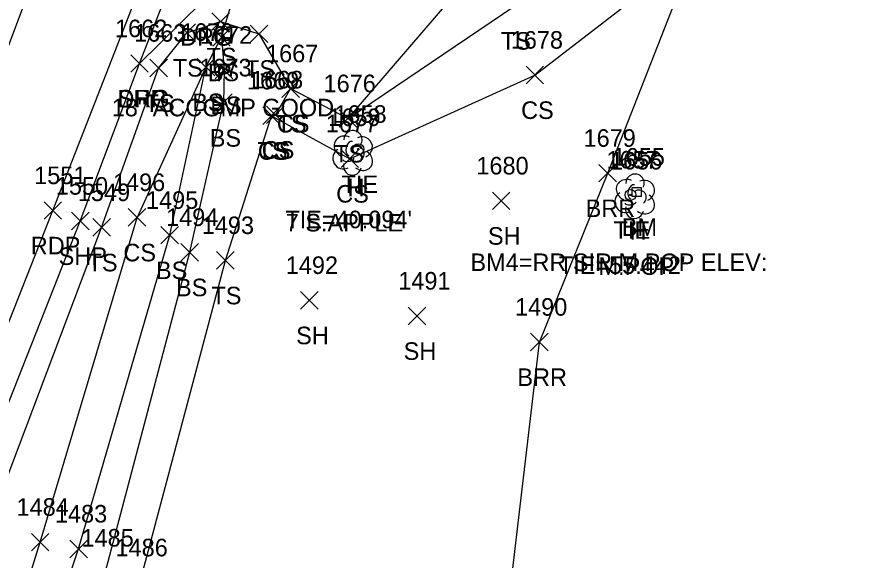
# Model space of a CAD drawing. Extents: x 1554917 to 1555870, y 813367 to 816333.
# Drawn here: x 1555258.8 to 1555355.3, y 814056.2 to 814118 of the extents above; entities that cross this region are included whole.
import ezdxf

# ---------------------------------------------------------------- set-up
doc = ezdxf.new("R2010")
doc.units = 0
for name, color, linetype in [('C_A', 7, 'Continuous'), ('C_C', 7, 'Continuous'), ('C_I', 7, 'Continuous'), ('CBP', 7, 'Continuous'), ('CPBM', 7, 'Continuous'), ('D_A', 7, 'Continuous'), ('D_C', 7, 'Continuous'), ('D_TIC', 7, 'Continuous'), ('DCP', 7, 'Continuous'), ('L_A', 7, 'Continuous'), ('L_C', 7, 'Continuous'), ('L_I', 7, 'Continuous'), ('L_TIC', 7, 'Continuous'), ('LABL', 7, 'Continuous'), ('LELB', 7, 'Continuous'), ('LTD', 7, 'Continuous'), ('P_A', 7, 'Continuous'), ('P_I', 7, 'Continuous'), ('P_TIC', 7, 'Continuous'), ('PET', 7, 'Continuous'), ('PRC', 7, 'Continuous'), ('PSP', 7, 'Continuous'), ('R_A', 7, 'Continuous'), ('R_I', 7, 'Continuous'), ('R_TIC', 7, 'Continuous'), ('RDG', 7, 'Continuous')]:
    doc.layers.add(name, color=color, linetype=linetype)

msp = doc.modelspace()

# ---------------------------------------------------------------- linework, layer by layer
at = {"layer": 'CBP'}
for centre, radius in [((1555297.714, 814102.983), 0.625), ((1555297.714, 814102.983), 0.0833), ((1555328.694, 814097.778), 0.625), ((1555328.694, 814097.778), 0.0833)]:
    msp.add_circle(centre, radius, dxfattribs=at)
at = {"layer": 'CPBM'}
for p, q in [((1555328.891, 814097.607), (1555328.891, 814098.607)), ((1555328.891, 814098.607), (1555329.891, 814098.607)), ((1555329.891, 814098.607), (1555329.891, 814097.607)), ((1555329.891, 814097.607), (1555328.891, 814097.607)), ((1555329.394, 814098.108), (1555329.394, 814098.108)), ((1555329.394, 814098.108), (1555329.394, 814098.108))]:
    msp.add_line(p, q, dxfattribs=at)
at = {"layer": 'D_TIC'}
for points in [[(1555281.121, 814114.724), (1555283.121, 814116.724)], [(1555283.121, 814114.724), (1555281.121, 814116.724)]]:
    msp.add_lwpolyline(points, dxfattribs=at)
at = {"layer": 'DCP'}
msp.add_lwpolyline([(1555282.121, 814115.724), (1555290.777, 814144.989)], dxfattribs=at)
at = {"layer": 'L_TIC'}
for points in [[(1555281.018, 814116.516), (1555283.018, 814118.516)], [(1555283.018, 814116.516), (1555281.018, 814118.516)], [(1555277.174, 814115.242), (1555279.174, 814117.242)], [(1555279.174, 814115.242), (1555277.174, 814117.242)], [(1555281.121, 814114.724), (1555283.121, 814116.724)], [(1555283.121, 814114.724), (1555281.121, 814116.724)], [(1555285.391, 814115.113), (1555287.391, 814117.113)], [(1555287.391, 814115.113), (1555285.391, 814117.113)], [(1555273.966, 814111.219), (1555275.966, 814113.219)], [(1555275.966, 814111.219), (1555273.966, 814113.219)], [(1555279.353, 814111.315), (1555281.353, 814113.315)], [(1555281.353, 814111.315), (1555279.353, 814113.315)], [(1555281.41, 814110.978), (1555283.41, 814112.978)], [(1555283.41, 814110.978), (1555281.41, 814112.978)], [(1555316.797, 814110.423), (1555318.797, 814112.423)], [(1555318.797, 814110.423), (1555316.797, 814112.423)], [(1555288.987, 814108.879), (1555290.987, 814110.879)], [(1555290.987, 814108.879), (1555288.987, 814110.879)], [(1555288.987, 814108.879), (1555290.987, 814110.879)], [(1555290.987, 814108.879), (1555288.987, 814110.879)], [(1555281.343, 814107.267), (1555283.343, 814109.267)], [(1555283.343, 814107.267), (1555281.343, 814109.267)], [(1555281.343, 814107.267), (1555283.343, 814109.267)], [(1555283.343, 814107.267), (1555281.343, 814109.267)], [(1555286.816, 814105.784), (1555288.816, 814107.784)], [(1555288.816, 814105.784), (1555286.816, 814107.784)], [(1555286.816, 814105.784), (1555288.816, 814107.784)], [(1555288.816, 814105.784), (1555286.816, 814107.784)], [(1555287.262, 814105.897), (1555289.262, 814107.897)], [(1555289.262, 814105.897), (1555287.262, 814107.897)], [(1555295.538, 814105.47), (1555297.538, 814107.47)], [(1555297.538, 814105.47), (1555295.538, 814107.47)], [(1555295.538, 814105.47), (1555297.538, 814107.47)], [(1555297.538, 814105.47), (1555295.538, 814107.47)], [(1555295.741, 814100.899), (1555297.741, 814102.899)], [(1555297.741, 814100.899), (1555295.741, 814102.899)], [(1555325.096, 814099.252), (1555327.096, 814101.252)], [(1555327.096, 814099.252), (1555325.096, 814101.252)], [(1555312.971, 814096.106), (1555314.971, 814098.106)], [(1555314.971, 814096.106), (1555312.971, 814098.106)], [(1555271.51, 814094.216), (1555273.51, 814096.216)], [(1555273.51, 814094.216), (1555271.51, 814096.216)], [(1555267.467, 814093.073), (1555269.467, 814095.073)], [(1555269.467, 814093.073), (1555267.467, 814095.073)], [(1555275.222, 814092.192), (1555277.222, 814094.192)], [(1555277.222, 814092.192), (1555275.222, 814094.192)], [(1555277.504, 814090.241), (1555279.504, 814092.241)], [(1555279.504, 814090.241), (1555277.504, 814092.241)], [(1555281.569, 814089.321), (1555283.569, 814091.321)], [(1555283.569, 814089.321), (1555281.569, 814091.321)], [(1555291.134, 814084.777), (1555293.134, 814086.777)], [(1555293.134, 814084.777), (1555291.134, 814086.777)], [(1555303.376, 814083.001), (1555305.376, 814085.001)], [(1555305.376, 814083.001), (1555303.376, 814085.001)], [(1555317.325, 814080.027), (1555319.325, 814082.027)], [(1555319.325, 814080.027), (1555317.325, 814082.027)], [(1555260.48, 814057.254), (1555262.48, 814059.254)], [(1555262.48, 814057.254), (1555260.48, 814059.254)], [(1555264.852, 814056.483), (1555266.852, 814058.483)], [(1555266.852, 814056.483), (1555264.852, 814058.483)]]:
    msp.add_lwpolyline(points, dxfattribs=at)
at = {"layer": 'LABL'}
msp.add_lwpolyline([(1555246.981, 813903.971), (1555255.509, 813921.275), (1555270.422, 813951.605), (1555277.93, 813973.793), (1555289.325, 813994.036), (1555300.327, 814008.734), (1555305.541, 814022.921), (1555313.635, 814041.095), (1555318.325, 814081.027), (1555326.096, 814100.252), (1555335.996, 814125.434)], dxfattribs=at)
at = {"layer": 'LELB'}
for points in [[(1555244.111, 813903.092), (1555240.763, 813916.624), (1555228.478, 813937.368), (1555217.606, 813950.51), (1555215.577, 813954.882), (1555216.988, 813960.621), (1555222.343, 813976.405), (1555235.006, 814010.769), (1555239.558, 814017.875), (1555245.781, 814033.085), (1555255.179, 814058.983), (1555268.467, 814094.073), (1555274.966, 814112.219), (1555278.174, 814116.242), (1555282.018, 814117.516), (1555286.391, 814116.113), (1555289.987, 814109.879), (1555296.538, 814106.47), (1555313.611, 814126.361), (1555333.567, 814137.643)], [(1555296.538, 814106.47), (1555315.529, 814119.309), (1555334.273, 814128.493)], [(1555289.987, 814109.879), (1555288.262, 814106.897), (1555287.816, 814106.784), (1555296.741, 814101.899), (1555317.797, 814111.423), (1555335.996, 814125.434)], [(1555246.981, 813903.971), (1555242.985, 813917.762), (1555232.876, 813938.625), (1555220.788, 813951.004), (1555219.558, 813956.099), (1555223.468, 813959.89), (1555224.609, 813963.071), (1555227.327, 813969.386), (1555236.622, 813985.651), (1555248.527, 814008.062), (1555259.52, 814030.523), (1555254.848, 814031.943), (1555257.997, 814033.776), (1555265.852, 814057.483), (1555276.222, 814093.192), (1555280.353, 814112.315), (1555282.121, 814115.724), (1555282.41, 814111.978), (1555282.343, 814108.267)], [(1555280.353, 814112.315), (1555272.51, 814095.216)], [(1555232.175, 813966.154), (1555239.587, 813985.718), (1555252.97, 814007.446), (1555261.299, 814028.56), (1555268.877, 814054.75), (1555278.504, 814091.241), (1555282.343, 814108.267)], [(1555232.175, 813966.154), (1555244.187, 813984.273), (1555255.579, 814006.592), (1555265.219, 814026.304), (1555272.807, 814053.636), (1555282.569, 814090.321), (1555287.816, 814106.784)], [(1555227.327, 813969.386), (1555232.893, 813986.643), (1555244.351, 814010.112), (1555253.33, 814032.08), (1555261.48, 814058.254), (1555272.51, 814095.216)]]:
    msp.add_lwpolyline(points, dxfattribs=at)
at = {"layer": 'LTD'}
for p, q in [((1555297.039, 814102.615), (1555297.039, 814102.615)), ((1555297.039, 814102.615), (1555297.039, 814102.615)), ((1555329.156, 814097.669), (1555329.156, 814097.669)), ((1555329.156, 814097.669), (1555329.156, 814097.669))]:
    msp.add_line(p, q, dxfattribs=at)
for centre in [(1555297.086, 814104.049), (1555329.202, 814099.103)]:
    msp.add_arc(centre, 1.047, 335.52715, 180.95627, dxfattribs=at)
for centre, major_axis, ratio, start_param, end_param in [((1555296.247, 814103.281), (1.21, -0.512), 0.895232, 1.570796, 4.712389), ((1555298.08, 814103.198), (-1.141, -0.483), 0.949671, 1.570796, 4.712389), ((1555296.83, 814103.073), (-0.208, -0.792), 0.645439, 3.141593, 6.283185), ((1555297.539, 814102.448), (-0.5, 0.667), 0.989748, 3.141593, 6.283185), ((1555295.956, 814101.906), (0.584, -1.042), 0.959034, 3.141593, 6.283185), ((1555298.039, 814101.782), (-1.09, 0.792), 0.841452, 1.570796, 4.712389), ((1555297.039, 814101.115), (0.265, 1.061), 0.942809, 1.570796, 4.712389), ((1555296.581, 814101.865), (-0.625, -0.083), 0.423636, 0, 3.141593), ((1555328.364, 814098.336), (1.21, -0.512), 0.895232, 1.570796, 4.712389), ((1555330.197, 814098.253), (-1.141, -0.483), 0.949671, 1.570796, 4.712389), ((1555328.947, 814098.127), (-0.208, -0.792), 0.645439, 3.141593, 6.283185), ((1555329.656, 814097.502), (-0.5, 0.667), 0.989748, 3.141593, 6.283185), ((1555328.072, 814096.961), (0.584, -1.042), 0.959034, 3.141593, 6.283185), ((1555330.156, 814096.836), (-1.09, 0.792), 0.841452, 1.570796, 4.712389), ((1555329.156, 814096.169), (0.265, 1.061), 0.942809, 1.570796, 4.712389), ((1555328.697, 814096.919), (-0.625, -0.083), 0.423636, 0, 3.141593)]:
    msp.add_ellipse(centre, major_axis=major_axis, ratio=ratio, start_param=start_param, end_param=end_param, dxfattribs=at)
at = {"layer": 'P_TIC'}
for points in [[(1555271.786, 814111.73), (1555273.786, 814113.73)], [(1555273.786, 814111.73), (1555271.786, 814113.73)], [(1555261.917, 814095.005), (1555263.917, 814097.005)], [(1555263.917, 814095.005), (1555261.917, 814097.005)], [(1555265.043, 814093.805), (1555267.043, 814095.805)], [(1555267.043, 814093.805), (1555265.043, 814095.805)]]:
    msp.add_lwpolyline(points, dxfattribs=at)
at = {"layer": 'PET'}
msp.add_lwpolyline([(1555182.568, 813892.252), (1555203.697, 813945.015), (1555216.848, 813978.344), (1555228.718, 814008.852), (1555239.472, 814035.465), (1555248.637, 814059.877), (1555262.917, 814096.005), (1555276.683, 814131.303), (1555286.362, 814156.334), (1555297.108, 814184.041), (1555306.669, 814209.508), (1555324.283, 814253.264), (1555340.351, 814293.545), (1555352.605, 814325.053)], dxfattribs=at)
at = {"layer": 'PRC'}
msp.add_lwpolyline([(1554976.762, 813382.178), (1554992.841, 813427.905), (1555014.068, 813486.005), (1555030.624, 813532.308), (1555046.369, 813573.085), (1555064.69, 813621.189), (1555082.406, 813667.527), (1555112.105, 813744.097), (1555110.691, 813739.792), (1555136.162, 813805.735), (1555152.521, 813846.933), (1555172.027, 813896.178), (1555193.956, 813951.204), (1555206.369, 813983.398), (1555218.126, 814013.217), (1555228.646, 814039.26), (1555237.929, 814064.306), (1555252.221, 814099.758), (1555265.8, 814135.892), (1555275.258, 814160.086), (1555297.17, 814214.772), (1555313.827, 814257.943), (1555329.72, 814298.264), (1555342.034, 814329.925)], dxfattribs=at)
at = {"layer": 'PSP'}
msp.add_lwpolyline([(1555197.674, 813922.422), (1555211.908, 813956.86), (1555220.23, 813977.153), (1555231.802, 814008.205), (1555242.477, 814034.479), (1555251.859, 814058.973), (1555266.043, 814094.805), (1555272.786, 814112.73), (1555286.228, 814147.196), (1555300.195, 814183.09), (1555310.337, 814208.216), (1555327.376, 814252.3), (1555343.486, 814292.443), (1555355.287, 814323.567)], dxfattribs=at)
at = {"layer": 'R_TIC'}
for points in [[(1555271.786, 814111.73), (1555273.786, 814113.73)], [(1555273.786, 814111.73), (1555271.786, 814113.73)]]:
    msp.add_lwpolyline(points, dxfattribs=at)
at = {"layer": 'RDG'}
msp.add_lwpolyline([(1555272.786, 814112.73), (1555279.927, 814119.76), (1555289.99, 814124.176), (1555311.522, 814130.978), (1555332.897, 814141.764)], dxfattribs=at)

# ---------------------------------------------------------------- texts
at = {"layer": 'C_A'}
for s, p in [('TIE', (1555295.793, 814097.983)), ('TIE', (1555326.773, 814092.778)), ('BM', (1555327.709, 814093.108))]:
    msp.add_text(s, height=2, dxfattribs=at).set_placement(p)
at = {"layer": 'C_C'}
for s, p in [("TIE=40.094'", (1555289.399, 814093.983)), ('BM4=RR SIR M.POP ELEV:', (1555310.465, 814089.108)), ("TIE=55.442'", (1555320.537, 814088.778))]:
    msp.add_text(s, height=2, dxfattribs=at).set_placement(p)
at = {"layer": 'C_I'}
for s, p in [('1658', (1555294.974, 814105.983)), ('1657', (1555325.954, 814100.778)), ('1655', (1555326.654, 814101.108))]:
    msp.add_text(s, height=2, dxfattribs=at).set_placement(p)
at = {"layer": 'D_A'}
msp.add_text('P', height=2, dxfattribs=at).set_placement((1555281.499, 814110.724))
at = {"layer": 'D_C'}
msp.add_text('18" ACCGMP GOOD', height=2, dxfattribs=at).set_placement((1555269.625, 814106.724))
at = {"layer": 'L_A'}
for s, p in [('TS', (1555313.939, 814114.309)), ('TS', (1555280.427, 814112.516)), ('TS', (1555276.583, 814111.242)), ('TS', (1555284.8, 814111.113)), ('BS', (1555280.562, 814110.724)), ('TS', (1555273.375, 814107.219)), ('BS', (1555278.794, 814107.315)), ('BS', (1555280.851, 814106.978)), ('CS', (1555316.238, 814106.423)), ('TS', (1555288.396, 814104.879)), ('CS', (1555288.428, 814104.879)), ('BS', (1555280.784, 814103.267)), ('BS', (1555280.784, 814103.267)), ('TS', (1555286.225, 814101.784)), ('CS', (1555286.257, 814101.784)), ('CS', (1555286.703, 814101.897)), ('TS', (1555294.947, 814101.47)), ('TS', (1555294.947, 814101.47)), ('H', (1555296.472, 814097.615)), ('CS', (1555295.182, 814096.899)), ('BRR', (1555323.584, 814095.252)), ('H', (1555328.589, 814092.669)), ('SH', (1555312.459, 814092.106)), ('CS', (1555270.951, 814090.216)), ('TS', (1555266.877, 814089.073)), ('BS', (1555274.663, 814088.192)), ('BS', (1555276.945, 814086.241)), ('TS', (1555280.978, 814085.321)), ('SH', (1555290.622, 814080.777)), ('SH', (1555302.864, 814079.001)), ('BRR', (1555315.813, 814076.027))]:
    msp.add_text(s, height=2, dxfattribs=at).set_placement(p)
at = {"layer": 'L_C'}
for s, p in [('7 S.APPLE', (1555289.433, 814093.615)), ('M.POP', (1555325.053, 814088.669))]:
    msp.add_text(s, height=2, dxfattribs=at).set_placement(p)
at = {"layer": 'L_I'}
for s, p in [('1663', (1555272.178, 814115.219)), ('1670', (1555277.526, 814115.315)), ('1672', (1555279.67, 814114.978)), ('1678', (1555315.057, 814114.423)), ('1667', (1555287.199, 814112.879)), ('1667', (1555287.199, 814112.879)), ('1673', (1555279.603, 814111.267)), ('1673', (1555279.603, 814111.267)), ('1668', (1555285.474, 814109.897)), ('1669', (1555285.02, 814109.784)), ('1669', (1555285.02, 814109.784)), ('1676', (1555293.743, 814109.47)), ('1676', (1555293.743, 814109.47)), ('1659', (1555294.291, 814105.615)), ('1677', (1555294.001, 814104.899)), ('1679', (1555323.348, 814103.252)), ('1656', (1555326.36, 814100.669)), ('1680', (1555311.144, 814100.106)), ('1496', (1555269.762, 814098.216)), ('1549', (1555265.767, 814097.073)), ('1495', (1555273.529, 814096.192)), ('1494', (1555275.812, 814094.241)), ('1493', (1555279.876, 814093.321)), ('1492', (1555289.441, 814088.777)), ('1491', (1555302.25, 814087.001)), ('1490', (1555315.545, 814084.027)), ('1484', (1555258.787, 814061.254)), ('1483', (1555263.159, 814060.483)), ('1485', (1555266.184, 814057.75)), ('1486', (1555270.059, 814056.636))]:
    msp.add_text(s, height=2, dxfattribs=at).set_placement(p)
at = {"layer": 'P_A'}
for s, p in [('SHP', (1555270.321, 814107.73)), ('RDP', (1555260.405, 814091.005)), ('SHP', (1555263.578, 814089.805))]:
    msp.add_text(s, height=2, dxfattribs=at).set_placement(p)
at = {"layer": 'P_I'}
for s, p in [('1662', (1555269.998, 814115.73)), ('1551', (1555260.791, 814099.005)), ('1550', (1555263.263, 814097.805))]:
    msp.add_text(s, height=2, dxfattribs=at).set_placement(p)
at = {"layer": 'R_A'}
for p in [(1555277.416, 814114.76), (1555270.274, 814107.73)]:
    msp.add_text('DRG', height=2, dxfattribs=at).set_placement(p)
at = {"layer": 'R_I'}
msp.add_text('1662', height=2, dxfattribs=at).set_placement((1555269.998, 814115.73))

doc.saveas('drawing.dxf')
